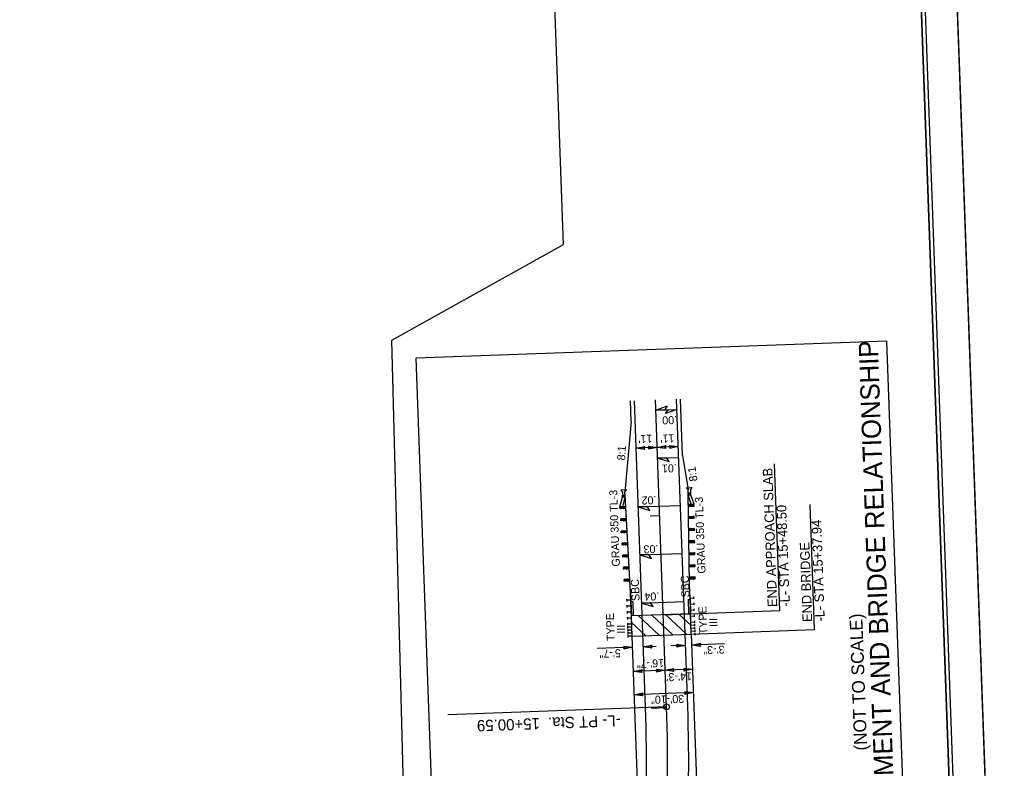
# Model space of a CAD drawing. Extents: x 2065068 to 2066582, y 144283 to 146300.
# Drawn here: x 2065965 to 2066582, y 144750 to 145217 of the extents above; entities that cross this region are included whole.
import ezdxf

# ---------------------------------------------------------------- set-up
doc = ezdxf.new("R2010")
doc.units = 0
for name, color, linetype in [('Prop Approach Slab', 7, 'Continuous'), ('Prop Approach Slab Hatching', 7, 'Continuous'), ('Prop Conc Shoulder Berm Gutter', 7, 'Continuous'), ('Prop Dimension', 7, 'Continuous'), ('Prop Dimension Text', 7, 'Continuous'), ('Prop EOT', 7, 'Continuous'), ('Prop Guardrail', 7, 'Continuous'), ('Prop Guardrail Anchor Unit CELL', 7, 'Continuous'), ('Prop Horizontal Alignment', 7, 'Continuous'), ('Prop Horizontal Alignment Station Label', 7, 'Continuous'), ('Prop Horizontal Alignment Tick Large', 7, 'Continuous'), ('Prop Horizontal Alignment Tick Small', 7, 'Continuous'), ('Prop Paved Shoulder', 7, 'Continuous'), ('Prop Roadway Bridge', 7, 'Continuous'), ('Prop Structure Anchor Unit CELL', 7, 'Continuous'), ('Prop Superelevation  Arrow CELL', 7, 'Continuous'), ('Prop Superelevation Label', 7, 'Continuous'), ('Prop Terminator CELL', 7, 'Continuous'), ('Sheet Clip Boundary CELL', 7, 'Continuous'), ('Sheet Cutting Line CELL', 7, 'Continuous'), ('Sheet Layout Plan Border', 7, 'Continuous'), ('Sheet Plan CELL', 7, 'Continuous'), ('Sheet Plan Layout CELL', 7, 'Continuous'), ('Sheet Plot Border Inside CELL', 7, 'Continuous'), ('Sheet Plot Border Outside CELL', 7, 'Continuous')]:
    doc.layers.add(name, color=color, linetype=linetype)

# ---------------------------------------------------------------- blocks, each defined once
blk = doc.blocks.new('Super Arrow Terminator')
at = {"layer": 'Prop Superelevation  Arrow CELL'}
blk.add_lwpolyline([(0, 0), (-6, -2), (-4.625, 0)], close=True, dxfattribs=at)

msp = doc.modelspace()

# ---------------------------------------------------------------- linework, layer by layer
at = {"layer": 'Prop Approach Slab'}
for p, q in [((2066384.03, 144846.34), (2066347.06, 144845)), ((2066347.52, 144832.34), (2066347.06, 144845)), ((2066384.49, 144833.67), (2066384.03, 144846.34))]:
    msp.add_line(p, q, dxfattribs=at)
at = {"layer": 'Prop Approach Slab Hatching'}
for p, q in [((2066364.48, 144832.95), (2066351.35, 144845.16)), ((2066372.95, 144833.26), (2066359.83, 144845.46)), ((2066381.43, 144833.56), (2066368.31, 144845.77)), ((2066384.29, 144839.1), (2066376.79, 144846.08)), ((2066356, 144832.64), (2066347.21, 144840.82))]:
    msp.add_line(p, q, dxfattribs=at)
at = {"layer": 'Prop Conc Shoulder Berm Gutter'}
for p, q in [((2066383.71, 144855.14), (2066382.51, 144855.1)), ((2066382.51, 144855.1), (2066382.83, 144846.29)), ((2066347.93, 144853.85), (2066346.74, 144853.8)), ((2066347.93, 144853.85), (2066348.25, 144845.04))]:
    msp.add_line(p, q, dxfattribs=at)
at = {"layer": 'Prop Dimension'}
for p, q in [((2066506.68, 145016.55), (2066212.56, 145005.92)), ((2066523.6, 144548.38), (2066506.68, 145016.55)), ((2066229.48, 144537.75), (2066212.56, 145005.92)), ((2066376.36, 144950.64), (2066349.97, 144949.68)), ((2066347.76, 144825.4), (2066325.64, 144824.6)), ((2066362.54, 144825.93), (2066354.46, 144825.64)), ((2066380.84, 144826.59), (2066371.66, 144826.26)), ((2066405.27, 144827.48), (2066384.74, 144826.74)), ((2066385.81, 144797.11), (2066348.83, 144795.77))]:
    msp.add_line(p, q, dxfattribs=at)
at = {"layer": 'Prop Dimension Text'}
msp.add_line((2066385.28, 144811.69), (2066348.31, 144810.35), dxfattribs=at)
at = {"layer": 'Prop EOT'}
for p, q in [((2066355.83, 144787.79), (2066348.9, 144979.32)), ((2066382.21, 144788.74), (2066375.29, 144980.28))]:
    msp.add_line(p, q, dxfattribs=at)
for radius, start in [(934.8, 349.99192), (961.2, 350.04596)]:
    msp.add_arc((2065421.64, 144754.02), radius, start, 2.07024, dxfattribs=at)
at = {"layer": 'Prop Guardrail'}
for p, q in [((2066346.45, 144861.79), (2066346.72, 144854.3)), ((2066383.69, 144855.63), (2066383.42, 144863.13))]:
    msp.add_line(p, q, dxfattribs=at)
at = {"layer": 'Prop Guardrail Anchor Unit CELL'}
for p, q in [((2066344.02, 144923.68), (2066340.5, 144923.55)), ((2066340.5, 144923.55), (2066341.58, 144922.18)), ((2066343.04, 144922.23), (2066344.02, 144923.68)), ((2066381.37, 144925.03), (2066384.9, 144925.16)), ((2066382.45, 144923.66), (2066381.37, 144925.03)), ((2066382.54, 144921.2), (2066382.45, 144923.66)), ((2066384.9, 144925.16), (2066383.92, 144923.71)), ((2066383.92, 144923.71), (2066384, 144921.25)), ((2066339.92, 144913.07), (2066341.47, 144919.05)), ((2066343.2, 144920.35), (2066341.4, 144920.24)), ((2066341.47, 144919.05), (2066341.4, 144920.24)), ((2066341.4, 144920.24), (2066343.26, 144919.15)), ((2066341.47, 144919.05), (2066341.43, 144919.65)), ((2066343.2, 144920.35), (2066341.47, 144919.05)), ((2066343.26, 144919.15), (2066341.47, 144919.05)), ((2066341.58, 144922.18), (2066341.67, 144919.72)), ((2066341.67, 144919.72), (2066342.4, 144919.75)), ((2066341.76, 144913.17), (2066343.26, 144919.15)), ((2066342.4, 144919.75), (2066343.14, 144919.78)), ((2066343.14, 144919.78), (2066343.04, 144922.23)), ((2066346.38, 144863.73), (2066343.23, 144919.75)), ((2066382.44, 144921.76), (2066384.24, 144921.79)), ((2066382.44, 144921.76), (2066384.26, 144920.59)), ((2066383.35, 144865.07), (2066382.45, 144921.16)), ((2066384.24, 144921.79), (2066382.46, 144920.56)), ((2066382.46, 144920.56), (2066384.26, 144920.59)), ((2066384.39, 144914.71), (2066382.46, 144920.56)), ((2066383.27, 144921.23), (2066382.54, 144921.2)), ((2066384, 144921.25), (2066383.27, 144921.23)), ((2066384.26, 144920.59), (2066384.24, 144921.79)), ((2066384.26, 144920.59), (2066384.25, 144921.19)), ((2066386.23, 144914.74), (2066384.26, 144920.59)), ((2066343.59, 144913.28), (2066339.92, 144913.07)), ((2066339.99, 144911.87), (2066339.92, 144913.07)), ((2066339.92, 144913.07), (2066341.82, 144911.97)), ((2066341.76, 144913.17), (2066339.99, 144911.87)), ((2066343.66, 144912.08), (2066339.99, 144911.87)), ((2066341.82, 144911.97), (2066341.76, 144913.17)), ((2066343.66, 144912.08), (2066341.76, 144913.17)), ((2066341.82, 144911.97), (2066343.59, 144913.28)), ((2066382.55, 144914.68), (2066386.23, 144914.74)), ((2066384.41, 144913.51), (2066382.55, 144914.68)), ((2066382.57, 144913.48), (2066384.39, 144914.71)), ((2066382.57, 144913.48), (2066386.25, 144913.54)), ((2066384.41, 144913.51), (2066384.39, 144914.71)), ((2066384.39, 144914.71), (2066386.25, 144913.54)), ((2066386.23, 144914.74), (2066384.41, 144913.51)), ((2066386.25, 144913.54), (2066386.23, 144914.74)), ((2066344.02, 144905.73), (2066340.42, 144905.52)), ((2066340.49, 144904.33), (2066340.42, 144905.52)), ((2066340.42, 144905.52), (2066342.29, 144904.43)), ((2066342.22, 144905.62), (2066340.49, 144904.33)), ((2066344.08, 144904.53), (2066340.49, 144904.33)), ((2066342.29, 144904.43), (2066342.22, 144905.62)), ((2066344.08, 144904.53), (2066342.22, 144905.62)), ((2066342.29, 144904.43), (2066344.02, 144905.73)), ((2066382.67, 144907.12), (2066386.27, 144907.18)), ((2066384.49, 144905.95), (2066382.67, 144907.12)), ((2066382.69, 144905.92), (2066384.47, 144907.15)), ((2066382.69, 144905.92), (2066386.29, 144905.98)), ((2066384.49, 144905.95), (2066384.47, 144907.15)), ((2066384.47, 144907.15), (2066386.29, 144905.98)), ((2066386.27, 144907.18), (2066384.49, 144905.95)), ((2066386.29, 144905.98), (2066386.27, 144907.18)), ((2066382.8, 144899.56), (2066386.56, 144899.62)), ((2066384.7, 144898.39), (2066382.8, 144899.56)), ((2066382.82, 144898.36), (2066384.68, 144899.59)), ((2066382.82, 144898.36), (2066386.58, 144898.42)), ((2066384.7, 144898.39), (2066384.68, 144899.59)), ((2066384.68, 144899.59), (2066386.58, 144898.42)), ((2066386.56, 144899.62), (2066384.7, 144898.39)), ((2066386.58, 144898.42), (2066386.56, 144899.62)), ((2066344.44, 144898.18), (2066340.68, 144897.96)), ((2066340.75, 144896.77), (2066340.68, 144897.96)), ((2066340.68, 144897.96), (2066342.63, 144896.87)), ((2066342.56, 144898.07), (2066340.75, 144896.77)), ((2066344.51, 144896.98), (2066340.75, 144896.77)), ((2066342.63, 144896.87), (2066342.56, 144898.07)), ((2066344.51, 144896.98), (2066342.56, 144898.07)), ((2066342.63, 144896.87), (2066344.44, 144898.18)), ((2066382.92, 144892), (2066386.56, 144892.06)), ((2066386.56, 144892.06), (2066384.76, 144890.83)), ((2066386.58, 144890.86), (2066386.56, 144892.06)), ((2066344.87, 144890.63), (2066341.23, 144890.42)), ((2066341.3, 144889.22), (2066341.23, 144890.42)), ((2066341.23, 144890.42), (2066343.11, 144889.33)), ((2066343.05, 144890.52), (2066341.3, 144889.22)), ((2066344.93, 144889.43), (2066341.3, 144889.22)), ((2066343.11, 144889.33), (2066343.05, 144890.52)), ((2066344.93, 144889.43), (2066343.05, 144890.52)), ((2066343.11, 144889.33), (2066344.87, 144890.63)), ((2066344.93, 144889.43), (2066344.87, 144890.63)), ((2066382.94, 144890.8), (2066382.92, 144892)), ((2066384.76, 144890.83), (2066382.92, 144892)), ((2066382.94, 144890.8), (2066384.74, 144892.03)), ((2066382.94, 144890.8), (2066386.58, 144890.86)), ((2066384.76, 144890.83), (2066384.74, 144892.03)), ((2066384.74, 144892.03), (2066386.58, 144890.86)), ((2066345.29, 144883.08), (2066341.64, 144882.87)), ((2066341.71, 144881.67), (2066341.64, 144882.87)), ((2066341.64, 144882.87), (2066343.53, 144881.78)), ((2066343.46, 144882.97), (2066341.71, 144881.67)), ((2066345.36, 144881.88), (2066341.71, 144881.67)), ((2066343.53, 144881.78), (2066343.46, 144882.97)), ((2066345.36, 144881.88), (2066343.46, 144882.97)), ((2066343.53, 144881.78), (2066345.29, 144883.08)), ((2066383.04, 144884.44), (2066386.7, 144884.5)), ((2066384.89, 144883.27), (2066383.04, 144884.44)), ((2066383.06, 144883.24), (2066384.87, 144884.47)), ((2066383.06, 144883.24), (2066386.72, 144883.3)), ((2066384.89, 144883.27), (2066384.87, 144884.47)), ((2066384.87, 144884.47), (2066386.72, 144883.3)), ((2066386.7, 144884.5), (2066384.89, 144883.27)), ((2066386.72, 144883.3), (2066386.7, 144884.5)), ((2066345.71, 144875.53), (2066342.06, 144875.32)), ((2066342.12, 144874.12), (2066342.06, 144875.32)), ((2066342.06, 144875.32), (2066343.95, 144874.23)), ((2066343.89, 144875.43), (2066342.12, 144874.12)), ((2066345.78, 144874.33), (2066342.12, 144874.12)), ((2066343.95, 144874.23), (2066343.89, 144875.43)), ((2066345.78, 144874.33), (2066343.89, 144875.43)), ((2066343.95, 144874.23), (2066345.71, 144875.53)), ((2066383.16, 144876.88), (2066386.82, 144876.94)), ((2066385.01, 144875.71), (2066383.16, 144876.88)), ((2066383.18, 144875.68), (2066384.99, 144876.91)), ((2066383.18, 144875.68), (2066386.84, 144875.74)), ((2066385.01, 144875.71), (2066384.99, 144876.91)), ((2066384.99, 144876.91), (2066386.84, 144875.74)), ((2066386.82, 144876.94), (2066385.01, 144875.71)), ((2066386.84, 144875.74), (2066386.82, 144876.94)), ((2066346.14, 144867.98), (2066342.54, 144867.78)), ((2066342.61, 144866.58), (2066342.54, 144867.78)), ((2066342.54, 144867.78), (2066344.41, 144866.68)), ((2066344.34, 144867.88), (2066342.61, 144866.58)), ((2066346.14, 144867.98), (2066344.34, 144867.88)), ((2066344.41, 144866.68), (2066344.34, 144867.88)), ((2066344.34, 144867.88), (2066346.21, 144866.78)), ((2066344.41, 144866.68), (2066346.14, 144867.98)), ((2066346.21, 144866.78), (2066346.14, 144867.98)), ((2066383.28, 144869.32), (2066386.88, 144869.38)), ((2066383.28, 144869.32), (2066385.08, 144869.35)), ((2066383.3, 144868.12), (2066383.28, 144869.32)), ((2066385.1, 144868.15), (2066383.28, 144869.32)), ((2066385.08, 144869.35), (2066383.3, 144868.12)), ((2066383.3, 144868.12), (2066386.9, 144868.18)), ((2066385.1, 144868.15), (2066385.08, 144869.35)), ((2066385.08, 144869.35), (2066386.9, 144868.18)), ((2066386.88, 144869.38), (2066385.1, 144868.15)), ((2066386.9, 144868.18), (2066386.88, 144869.38)), ((2066346.21, 144866.78), (2066342.61, 144866.58))]:
    msp.add_line(p, q, dxfattribs=at)
at = {"layer": 'Prop Horizontal Alignment'}
msp.add_line((2066369.02, 144788.26), (2066362.09, 144979.8), dxfattribs=at)
msp.add_arc((2065421.64, 144754.02), 948, 350.00503, 2.07024, dxfattribs=at)
at = {"layer": 'Prop Horizontal Alignment Station Label'}
for p, q in [((2066439.82, 144848.35), (2066436.5, 144939.98)), ((2066461.48, 144836.46), (2066458.65, 144914.51)), ((2066366.94, 144845.72), (2066439.82, 144848.35)), ((2066367.4, 144833.06), (2066461.48, 144836.46)), ((2066369.02, 144788.26), (2066232.31, 144783.32))]:
    msp.add_line(p, q, dxfattribs=at)
msp.add_circle((2066369.02, 144788.26), 1.8, dxfattribs=at)
at = {"layer": 'Prop Horizontal Alignment Tick Large'}
msp.add_line((2066369.04, 144787.56), (2066359.45, 144787.22), dxfattribs=at)
at = {"layer": 'Prop Horizontal Alignment Tick Small'}
msp.add_line((2066364.71, 144907.48), (2066358.71, 144907.26), dxfattribs=at)
at = {"layer": 'Prop Paved Shoulder'}
for p, q in [((2066346.97, 144966.27), (2066346.5, 144979.23)), ((2066378.96, 144945.15), (2066377.68, 144980.36)), ((2066346.97, 144966.27), (2066343.04, 144922.23)), ((2066378.96, 144945.15), (2066382.45, 144923.66)), ((2066346.72, 144854.3), (2066346.38, 144863.73)), ((2066383.69, 144855.64), (2066383.35, 144865.07)), ((2066383.69, 144855.64), (2066384.03, 144846.34)), ((2066346.72, 144854.3), (2066347.05, 144845))]:
    msp.add_line(p, q, dxfattribs=at)
for points in [[(2066383.35, 144865.07), (2066382.44, 144921.76), (2066382.45, 144923.66)], [(2066346.38, 144863.73), (2066343.2, 144920.35), (2066343.04, 144922.23)]]:
    msp.add_lwpolyline(points, dxfattribs=at)
at = {"layer": 'Prop Roadway Bridge'}
for p, q in [((2066347.52, 144832.34), (2066384.49, 144833.67)), ((2066351.02, 144735.37), (2066347.52, 144832.34)), ((2066384.49, 144833.67), (2066387.99, 144736.71))]:
    msp.add_line(p, q, dxfattribs=at)
at = {"layer": 'Prop Structure Anchor Unit CELL'}
for p, q in [((2066344.33, 144854.05), (2066344.28, 144855.42)), ((2066383.67, 144856.16), (2066386.07, 144856.25)), ((2066384.49, 144833.67), (2066383.67, 144856.16)), ((2066386.1, 144855.56), (2066386.05, 144856.93)), ((2066346.7, 144854.82), (2066344.3, 144854.74)), ((2066344.46, 144850.3), (2066344.42, 144851.68)), ((2066346.84, 144851.08), (2066344.44, 144850.99)), ((2066347.52, 144832.34), (2066346.7, 144854.82)), ((2066383.81, 144852.41), (2066386.21, 144852.5)), ((2066386.23, 144851.81), (2066386.18, 144853.19)), ((2066386.37, 144848.06), (2066386.32, 144849.44)), ((2066344.6, 144846.55), (2066344.55, 144847.93)), ((2066346.97, 144847.33), (2066344.58, 144847.24)), ((2066344.74, 144842.81), (2066344.69, 144844.18)), ((2066347.11, 144843.58), (2066344.71, 144843.49)), ((2066383.95, 144848.66), (2066386.34, 144848.75)), ((2066384.08, 144844.92), (2066386.48, 144845)), ((2066386.5, 144844.32), (2066386.45, 144845.69)), ((2066344.87, 144839.06), (2066344.82, 144840.43)), ((2066347.24, 144839.83), (2066344.85, 144839.75)), ((2066344.94, 144837.19), (2066344.89, 144838.56)), ((2066347.31, 144837.96), (2066344.91, 144837.87)), ((2066345.01, 144835.31), (2066344.96, 144836.69)), ((2066384.22, 144841.17), (2066386.61, 144841.26)), ((2066384.28, 144839.3), (2066386.68, 144839.38)), ((2066384.35, 144837.42), (2066386.75, 144837.51)), ((2066386.64, 144840.57), (2066386.59, 144841.94)), ((2066386.71, 144838.7), (2066386.66, 144840.07)), ((2066386.78, 144836.82), (2066386.73, 144838.2)), ((2066347.38, 144836.09), (2066344.98, 144836)), ((2066345.07, 144833.44), (2066345.02, 144834.81)), ((2066347.45, 144834.21), (2066345.05, 144834.12)), ((2066345.14, 144831.56), (2066345.09, 144832.94)), ((2066347.52, 144832.34), (2066345.12, 144832.25)), ((2066384.42, 144835.55), (2066386.82, 144835.63)), ((2066384.49, 144833.67), (2066386.89, 144833.76)), ((2066386.84, 144834.95), (2066386.79, 144836.32)), ((2066386.91, 144833.07), (2066386.86, 144834.45))]:
    msp.add_line(p, q, dxfattribs=at)
at = {"layer": 'Prop Superelevation  Arrow CELL'}
for p, q in [((2066362.32, 144973.44), (2066375.52, 144973.91)), ((2066363.41, 144943.46), (2066376.6, 144943.93)), ((2066351.3, 144913), (2066377.68, 144913.95)), ((2066352.38, 144883.02), (2066378.77, 144883.97)), ((2066353.47, 144853.04), (2066379.85, 144853.99))]:
    msp.add_line(p, q, dxfattribs=at)
at = {"layer": 'Prop Terminator CELL'}
for points in [[(2066355.4, 144948.95), (2066349.97, 144949.68), (2066355.37, 144950.84), (2066354.71, 144949.85)], [(2066357.74, 144950.89), (2066363.17, 144950.16), (2066357.77, 144949), (2066358.43, 144949.99)], [(2066368.6, 144949.43), (2066363.17, 144950.16), (2066368.56, 144951.32), (2066367.9, 144950.33)], [(2066370.93, 144951.37), (2066376.36, 144950.64), (2066370.97, 144949.48), (2066371.62, 144950.47)], [(2066342.33, 144826.13), (2066347.76, 144825.4), (2066342.37, 144824.24), (2066343.03, 144825.23)], [(2066359.89, 144824.91), (2066354.46, 144825.64), (2066359.85, 144826.8), (2066359.19, 144825.81)], [(2066375.41, 144827.33), (2066380.84, 144826.59), (2066375.45, 144825.44), (2066376.1, 144826.42)], [(2066390.17, 144826), (2066384.74, 144826.74), (2066390.13, 144827.89), (2066389.48, 144826.91)], [(2066362.76, 144811.81), (2066368.19, 144811.07), (2066362.8, 144809.92), (2066363.46, 144810.9)], [(2066373.62, 144810.34), (2066368.19, 144811.07), (2066373.59, 144812.23), (2066372.93, 144811.24)], [(2066379.85, 144812.42), (2066385.28, 144811.69), (2066379.89, 144810.53), (2066380.55, 144811.52)], [(2066353.74, 144809.62), (2066348.31, 144810.35), (2066353.7, 144811.51), (2066353.05, 144810.52)], [(2066354.26, 144795.04), (2066348.83, 144795.77), (2066354.23, 144796.93), (2066353.57, 144795.94)], [(2066380.38, 144797.84), (2066385.81, 144797.11), (2066380.42, 144795.95), (2066381.07, 144796.94)]]:
    msp.add_lwpolyline(points, close=True, dxfattribs=at)
at = {"layer": 'Sheet Clip Boundary CELL'}
msp.add_lwpolyline([(2066209.26, 144563.12), (2066197.36, 145017.22), (2066304.56, 145076.85), (2066276.35, 145857.16), (2065667.01, 145835.13), (2065670.41, 145741.24), (2065591.32, 145738.38), (2065521, 144770.65), (2065527.51, 144606.5), (2065634.3, 144549.42)], close=True, dxfattribs=at)
at = {"layer": 'Sheet Cutting Line CELL'}
msp.add_line((2066582.43, 144346.04), (2066521.61, 146028.44), dxfattribs=at)
at = {"layer": 'Sheet Layout Plan Border'}
msp.add_lwpolyline([(2066552.11, 144561.57), (2066501.53, 145960.67), (2065663.57, 145930.38), (2065670.41, 145741.24), (2065459.06, 145733.6), (2065502.79, 144523.64)], close=True, dxfattribs=at)
at = {"layer": 'Sheet Plan CELL'}
for points in [[(2065450.41, 145972.73), (2065504.6, 144473.67), (2066553.91, 144511.61), (2066499.73, 146010.64)], [(2066553.91, 144511.61), (2065504.63, 144473.65), (2065457.63, 145772.79), (2065607.59, 145778.22), (2065600.38, 145978.13), (2066499.73, 146010.64)]]:
    msp.add_lwpolyline(points, close=True, dxfattribs=at)
at = {"layer": 'Sheet Plan Layout CELL'}
msp.add_lwpolyline([(2065504.63, 144473.65), (2066553.91, 144511.61), (2066499.73, 146010.63), (2065661.76, 145980.34), (2065670.41, 145741.24), (2065459.06, 145733.6)], close=True, dxfattribs=at)
at = {"layer": 'Sheet Plot Border Inside CELL'}
msp.add_lwpolyline([(2066561.97, 144358.31), (2066501.77, 146023.21), (2065447.47, 145985.11), (2065507.66, 144320.2)], close=True, dxfattribs=at)
at = {"layer": 'Sheet Plot Border Outside CELL'}
msp.add_lwpolyline([(2066582.43, 144346.04), (2066521.61, 146028.44), (2065427.33, 145988.88), (2065488.14, 144306.48)], close=True, dxfattribs=at)

# ---------------------------------------------------------------- block references
at = {"layer": 'Prop Superelevation  Arrow CELL'}
for p, xscale, yscale, rotation in [((2066362.32, 144973.44), 1.1999976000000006, 1.1999976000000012, -177.92975555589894), ((2066375.52, 144973.91), 1.1999976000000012, 1.1999976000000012, 2.0702444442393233), ((2066363.41, 144943.46), 1.1999976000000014, -1.199997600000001, -177.92975555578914), ((2066351.3, 144913), 1.1999976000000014, -1.1999976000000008, -177.9297555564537), ((2066352.38, 144883.02), 1.1999976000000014, -1.1999976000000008, -177.9297555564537), ((2066353.47, 144853.04), 1.1999976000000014, -1.1999976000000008, -177.9297555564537)]:
    msp.add_blockref('Super Arrow Terminator', p, dxfattribs=dict(at, xscale=xscale, yscale=yscale, rotation=rotation))

# ---------------------------------------------------------------- texts
at = {"layer": 'Prop Dimension'}
for s, height, p in [('DETAIL SHOWING PAVEMENT AND BRIDGE RELATIONSHIP', 12, (2066517.48, 144559.09)), ('(NOT TO SCALE)', 8, (2066494.31, 144761.08))]:
    msp.add_text(s, height=height, rotation=92.07024, dxfattribs=at).set_placement(p)
at = {"layer": 'Prop Dimension Text'}
for s, rotation, p in [("11'", 182.07024, (2066360.07, 144958.15)), ("11'", 182.07024, (2066373.83, 144958.42)), ('8:1', 86.19987, (2066343.07, 144941.89)), ('8:1', 98.21621, (2066388.35, 144929.28)), ('SBC', 92.07024, (2066352.21, 144854.35)), ('SBC', 92.07024, (2066383.37, 144856.62)), ('5\'-7"', 182.07024, (2066340.36, 144824.27)), ('3\'-3"', 182.07024, (2066405.19, 144826.52)), ('16\'-7"', 182.07024, (2066367.4, 144818.07)), ('14\'-3"', 182.07024, (2066384.79, 144809.77)), ('30\'-10"', 182.07024, (2066379.97, 144795.79))]:
    msp.add_text(s, height=5, rotation=rotation, dxfattribs=at).set_placement(p)
at = {"layer": 'Prop Guardrail Anchor Unit CELL'}
for p in [(2066339.9, 144875.89), (2066393.4, 144871.48)]:
    msp.add_text('GRAU 350 TL-3', height=5, rotation=92.07024, dxfattribs=at).set_placement(p)
at = {"layer": 'Prop Horizontal Alignment Station Label'}
for s, height, rotation, p in [('END APPROACH SLAB', 6, 92.07024, (2066438.18, 144850.61)), ('-L- STA 15+48.50', 6, 92.07024, (2066446.04, 144850.89)), ('-L- STA 15+37.94', 6, 92.07024, (2066467.86, 144841.58)), ('END BRIDGE', 6, 92.07024, (2066460, 144841.29)), ('-L- PT Sta.  15+00.59', 7, 182.07024, (2066340.19, 144783.12))]:
    msp.add_text(s, height=height, rotation=rotation, dxfattribs=at).set_placement(p)
at = {"layer": 'Prop Structure Anchor Unit CELL'}
for s, p in [('TYPE', (2066394.49, 144833.59)), ('TYPE', (2066336.76, 144829.38)), ('III', (2066400.88, 144838.22)), ('III', (2066343.15, 144834.01))]:
    msp.add_text(s, height=5, rotation=92.07024, dxfattribs=at).set_placement(p)
at = {"layer": 'Prop Superelevation Label'}
for s, p in [('.00', (2066375.54, 144969.84)), ('.01', (2066375.32, 144939.75)), ('.02', (2066362.63, 144919.8)), ('.03', (2066363.84, 144889.32)), ('.04', (2066364.4, 144859.78))]:
    msp.add_text(s, height=5, rotation=182.07024, dxfattribs=at).set_placement(p)

doc.saveas('drawing.dxf')
